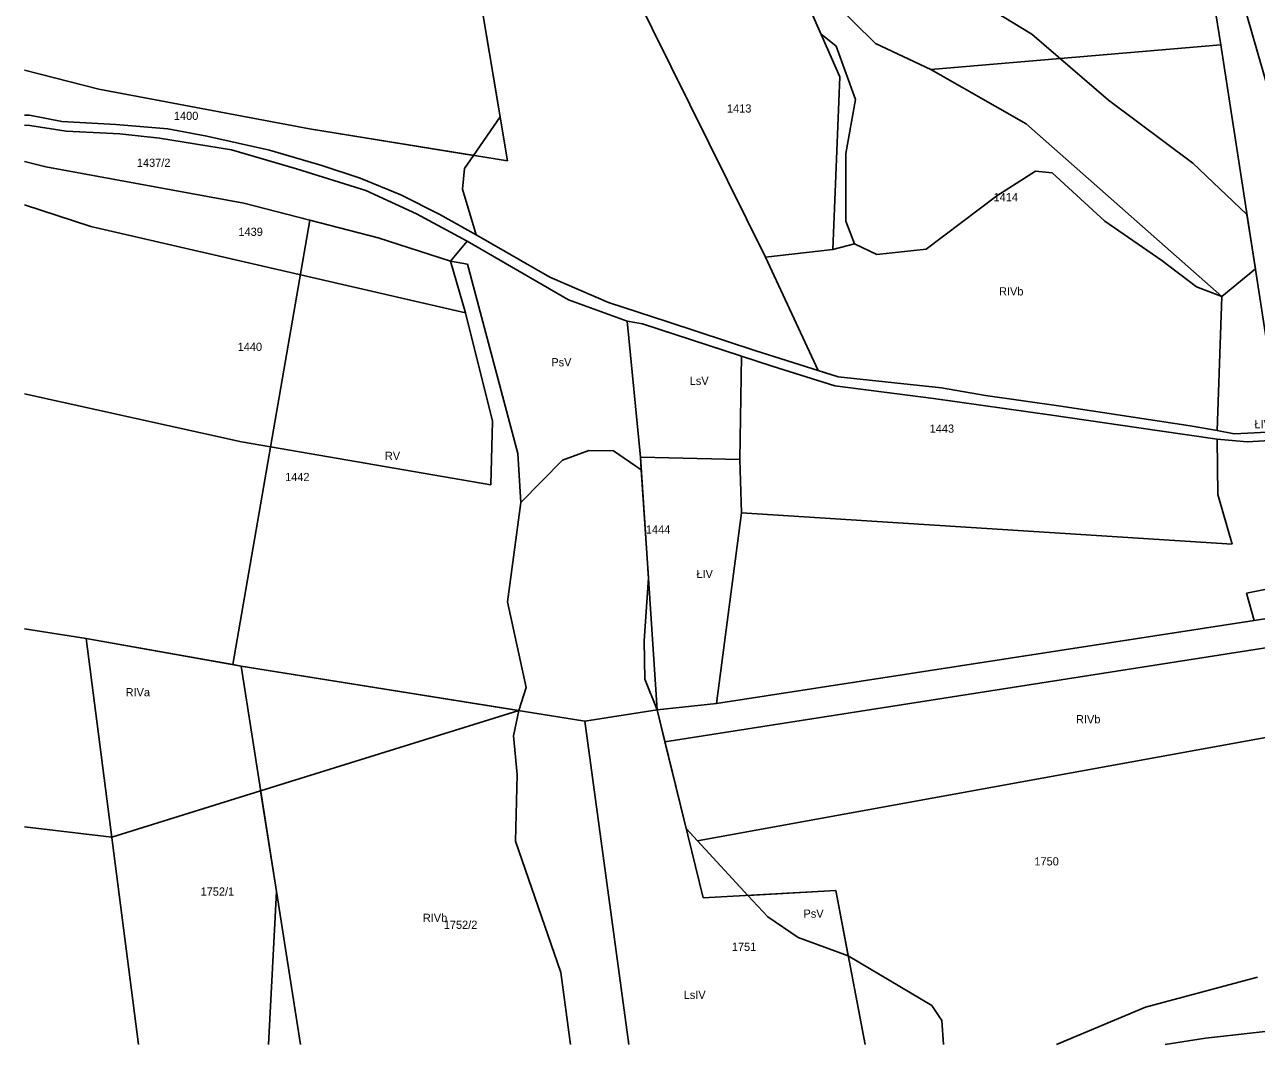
# Model space of a CAD drawing. Extents: x 7498273 to 7499989, y 5499795 to 5500810.
# Drawn here: x 7498273.2 to 7498498.5, y 5499795 to 5499981.5 of the extents above; entities that cross this region are included whole.
import ezdxf

# ---------------------------------------------------------------- set-up
doc = ezdxf.new("R2010")
doc.units = 0
for name, color, linetype in [('209-oznaczenie konturu klasyfikacyjnego', 7, 'Continuous'), ('211-numer działki ewidencyjnej', 7, 'Continuous'), ('217-kontur klasyfikacyjny', 7, 'Continuous'), ('218-kontur użytku gruntowego', 7, 'Continuous'), ('219-działka ewidencyjna', 7, 'Continuous')]:
    doc.layers.add(name, color=color, linetype=linetype)

msp = doc.modelspace()

# ---------------------------------------------------------------- linework, layer by layer
at = {"layer": '217-kontur klasyfikacyjny'}
for points in [[(7498492.44, 5499998.12), (7498509.38, 5499939.22)], [(7498354.96, 5499995.54), (7498360.15, 5499964.66)], [(7498408.66, 5499938.97), (7498380.98, 5499994.84)], [(7498418.82, 5499979.84), (7498412.52, 5499994.14)], [(7498457.42, 5499979.76), (7498434.61, 5499993.64)], [(7498421.58, 5499977.57), (7498418.82, 5499979.84)], [(7498471.4, 5499967.66), (7498457.42, 5499979.76)], [(7498425.12, 5499967.83), (7498421.58, 5499977.57)], [(7498286.77, 5499969.72), (7498273.174, 5499973.159)], [(7498325.25, 5499962.42), (7498286.77, 5499969.72)], [(7498423.36, 5499957.93), (7498425.12, 5499967.83)], [(7498486.83, 5499956.17), (7498471.4, 5499967.66)], [(7498273.174, 5499964.916), (7498274.04, 5499964.92)], [(7498274.1, 5499963.05), (7498273.174, 5499963.083)], [(7498274.04, 5499964.92), (7498280, 5499963.77)], [(7498280.77, 5499962.01), (7498274.1, 5499963.05)], [(7498280, 5499963.77), (7498289.88, 5499963.23)], [(7498289.88, 5499963.23), (7498299.34, 5499962.42)], [(7498360.15, 5499964.66), (7498355.27, 5499957.57)], [(7498290.57, 5499961.54), (7498280.77, 5499962.01)], [(7498297.84, 5499960.74), (7498290.57, 5499961.54)], [(7498311.03, 5499958.63), (7498297.84, 5499960.74)], [(7498299.34, 5499962.42), (7498306.49, 5499961.07)], [(7498306.49, 5499961.07), (7498317.96, 5499958.57)], [(7498355.27, 5499957.57), (7498325.25, 5499962.42)], [(7498322.89, 5499955.12), (7498311.03, 5499958.63)], [(7498317.96, 5499958.57), (7498327.52, 5499955.71)], [(7498277.07, 5499955.51), (7498273.174, 5499956.484)], [(7498355.27, 5499957.57), (7498353.64, 5499955.19)], [(7498423.37, 5499945.57), (7498423.36, 5499957.93)], [(7498496.74, 5499946.78), (7498486.83, 5499956.17)], [(7498313.28, 5499948.82), (7498277.07, 5499955.51)], [(7498335.56, 5499951.18), (7498322.89, 5499955.12)], [(7498327.52, 5499955.71), (7498334.52, 5499953.43)], [(7498353.64, 5499955.19), (7498353.27, 5499951.4)], [(7498451.01, 5499950.2), (7498458.04, 5499954.69)], [(7498458.04, 5499954.69), (7498461.14, 5499954.38)], [(7498461.14, 5499954.38), (7498470.75, 5499945.58)], [(7498334.52, 5499953.43), (7498341.99, 5499950.39)], [(7498344.87, 5499946.88), (7498335.56, 5499951.18)], [(7498341.99, 5499950.39), (7498349.09, 5499946.77)], [(7498353.27, 5499951.4), (7498355.77, 5499943.08)], [(7498438.1, 5499940.41), (7498451.01, 5499950.2)], [(7498325.35, 5499945.73), (7498313.28, 5499948.82)], [(7498311.26, 5499864.47), (7498325.35, 5499945.73)], [(7498337.86, 5499942.52), (7498325.35, 5499945.73)], [(7498354.11, 5499941.89), (7498344.87, 5499946.88)], [(7498349.09, 5499946.77), (7498355.77, 5499943.08)], [(7498424.96, 5499941.43), (7498423.37, 5499945.57)], [(7498470.75, 5499945.58), (7498481.19, 5499938.38)], [(7498498.28, 5499936.82), (7498496.74, 5499946.78)], [(7498355.77, 5499943.08), (7498369.24, 5499935.29)], [(7498351.05, 5499938.24), (7498337.86, 5499942.52)], [(7498354.11, 5499941.89), (7498351.05, 5499938.24)], [(7498372.63, 5499931.15), (7498354.11, 5499941.89)], [(7498408.66, 5499938.97), (7498421.01, 5499940.39)], [(7498421.01, 5499940.39), (7498424.96, 5499941.43)], [(7498424.96, 5499941.43), (7498429.05, 5499939.45)], [(7498429.05, 5499939.45), (7498438.1, 5499940.41)], [(7498354.17, 5499937.71), (7498351.05, 5499938.24)], [(7498418.29, 5499918.22), (7498408.66, 5499938.97)], [(7498481.19, 5499938.38), (7498487.52, 5499933.55)], [(7498363.38, 5499903.05), (7498354.17, 5499937.71)], [(7498492.13, 5499931.8), (7498498.28, 5499936.82)], [(7498369.24, 5499935.29), (7498379.95, 5499930.71)], [(7498487.52, 5499933.55), (7498492.13, 5499931.8)], [(7498491.3, 5499907.25), (7498492.13, 5499931.8)], [(7498383.38, 5499927.26), (7498372.63, 5499931.15)], [(7498379.95, 5499930.71), (7498390.84, 5499927.12)], [(7498385.8, 5499902.41), (7498383.38, 5499927.26)], [(7498386.19, 5499926.76), (7498383.38, 5499927.26)], [(7498390.84, 5499927.12), (7498406.9, 5499921.86)], [(7498404.28, 5499920.89), (7498386.19, 5499926.76)], [(7498404.01, 5499901.96), (7498404.28, 5499920.89)], [(7498409.92, 5499919.06), (7498404.28, 5499920.89)], [(7498406.9, 5499921.86), (7498418.29, 5499918.22)], [(7498421.37, 5499915.45), (7498409.92, 5499919.06)], [(7498418.29, 5499918.22), (7498421.95, 5499917.1)], [(7498421.95, 5499917.1), (7498440.9, 5499915.08)], [(7498439.43, 5499913.11), (7498421.37, 5499915.45)], [(7498440.9, 5499915.08), (7498448.94, 5499913.66)], [(7498448.94, 5499913.66), (7498462.71, 5499911.75)], [(7498461.03, 5499910.05), (7498439.43, 5499913.11)], [(7498462.71, 5499911.75), (7498486.33, 5499908.13)], [(7498480.32, 5499907.27), (7498461.03, 5499910.05)], [(7498491.31, 5499905.72), (7498480.32, 5499907.27)], [(7498486.33, 5499908.13), (7498491.3, 5499907.25)], [(7498491.3, 5499907.25), (7498494.41, 5499906.69)], [(7498494.41, 5499906.69), (7498502.88, 5499907.08)], [(7498496.76, 5499905.22), (7498491.31, 5499905.72)], [(7498506.1, 5499905.78), (7498496.76, 5499905.22)], [(7498363.96, 5499894.14), (7498363.38, 5499903.05)], [(7498371.56, 5499901.85), (7498376.39, 5499903.64)], [(7498376.39, 5499903.64), (7498380.88, 5499903.57)], [(7498380.88, 5499903.57), (7498385.96, 5499900.06)], [(7498385.96, 5499900.06), (7498385.8, 5499902.41)], [(7498385.8, 5499902.41), (7498404.01, 5499901.96)], [(7498363.96, 5499894.14), (7498371.56, 5499901.85)], [(7498387.26, 5499880.34), (7498385.96, 5499900.06)], [(7498404.29, 5499892.2), (7498404.01, 5499901.96)], [(7498361.47, 5499875.92), (7498363.96, 5499894.14)], [(7498399.75, 5499857.33), (7498404.29, 5499892.2)], [(7498386.47, 5499868.8), (7498387.26, 5499880.34)], [(7498364.88, 5499860.25), (7498361.47, 5499875.92)], [(7498522.06, 5499876.32), (7498498.06, 5499872.53)], [(7498390.29, 5499850.35), (7498536.44, 5499873.21)], [(7498273.174, 5499871.028), (7498284.45, 5499869.26)], [(7498498.06, 5499872.53), (7498399.75, 5499857.33)], [(7498284.45, 5499869.26), (7498311.26, 5499864.47)], [(7498386.64, 5499861.78), (7498386.47, 5499868.8)], [(7498312.75, 5499864.2), (7498311.26, 5499864.47)], [(7498363.59, 5499856.07), (7498312.75, 5499864.2)], [(7498388.86, 5499856.17), (7498386.64, 5499861.78)], [(7498363.59, 5499856.07), (7498364.88, 5499860.25)], [(7498388.86, 5499856.17), (7498399.75, 5499857.33)], [(7498316.34, 5499841.37), (7498363.59, 5499856.07)], [(7498362.57, 5499851.43), (7498363.59, 5499856.07)], [(7498390.29, 5499850.35), (7498388.86, 5499856.17)], [(7498396.23, 5499832.25), (7498509.2, 5499852.81)], [(7498363.26, 5499844.39), (7498362.57, 5499851.43)], [(7498394.17, 5499834.48), (7498390.29, 5499850.35)], [(7498362.96, 5499832.16), (7498363.26, 5499844.39)], [(7498316.34, 5499841.37), (7498289.14, 5499832.91)], [(7498319.23, 5499822.98), (7498316.34, 5499841.37)], [(7498289.14, 5499832.91), (7498273.174, 5499834.791)], [(7498396.23, 5499832.25), (7498394.17, 5499834.48)], [(7498405.44, 5499822.27), (7498396.23, 5499832.25)], [(7498371.24, 5499808.14), (7498362.96, 5499832.16)], [(7498405.44, 5499822.27), (7498421.52, 5499823.16)], [(7498421.52, 5499823.16), (7498423.82, 5499811.19)], [(7498317.762, 5499795.022), (7498319.23, 5499822.98)], [(7498409.08, 5499818.32), (7498405.44, 5499822.27)], [(7498414.63, 5499814.55), (7498409.08, 5499818.32)], [(7498423.82, 5499811.19), (7498414.63, 5499814.55)], [(7498439.12, 5499802.14), (7498423.82, 5499811.19)], [(7498372.991, 5499795.022), (7498371.24, 5499808.14)], [(7498498.65, 5499807.28), (7498478.18, 5499801.81)], [(7498440.95, 5499799.37), (7498439.12, 5499802.14)], [(7498478.18, 5499801.81), (7498461.907, 5499795.022)], [(7498441.257, 5499795.022), (7498440.95, 5499799.37)], [(7498489.18, 5499796.13), (7498526.87, 5499800.36)], [(7498481.788, 5499795.022), (7498489.18, 5499796.13)]]:
    msp.add_lwpolyline(points, dxfattribs=at)
at = {"layer": '218-kontur użytku gruntowego'}
for points in [[(7498492.44, 5499998.12), (7498509.38, 5499939.22)], [(7498360.15, 5499964.66), (7498354.96, 5499995.54)], [(7498380.98, 5499994.84), (7498408.66, 5499938.97)], [(7498412.52, 5499994.14), (7498418.82, 5499979.84)], [(7498457.42, 5499979.76), (7498434.61, 5499993.64)], [(7498418.82, 5499979.84), (7498421.58, 5499977.57)], [(7498471.4, 5499967.66), (7498457.42, 5499979.76)], [(7498421.58, 5499977.57), (7498425.12, 5499967.83)], [(7498273.174, 5499973.159), (7498286.77, 5499969.72)], [(7498286.77, 5499969.72), (7498325.25, 5499962.42)], [(7498425.12, 5499967.83), (7498423.36, 5499957.93)], [(7498486.83, 5499956.17), (7498471.4, 5499967.66)], [(7498273.174, 5499964.916), (7498274.04, 5499964.92)], [(7498274.1, 5499963.05), (7498273.174, 5499963.083)], [(7498274.04, 5499964.92), (7498280, 5499963.77)], [(7498280.77, 5499962.01), (7498274.1, 5499963.05)], [(7498280, 5499963.77), (7498289.88, 5499963.23)], [(7498289.88, 5499963.23), (7498299.34, 5499962.42)], [(7498355.27, 5499957.57), (7498360.15, 5499964.66)], [(7498290.57, 5499961.54), (7498280.77, 5499962.01)], [(7498297.84, 5499960.74), (7498290.57, 5499961.54)], [(7498311.03, 5499958.63), (7498297.84, 5499960.74)], [(7498299.34, 5499962.42), (7498306.49, 5499961.07)], [(7498306.49, 5499961.07), (7498317.96, 5499958.57)], [(7498325.25, 5499962.42), (7498355.27, 5499957.57)], [(7498322.89, 5499955.12), (7498311.03, 5499958.63)], [(7498317.96, 5499958.57), (7498327.52, 5499955.71)], [(7498277.07, 5499955.51), (7498273.174, 5499956.484)], [(7498353.64, 5499955.19), (7498355.27, 5499957.57)], [(7498423.36, 5499957.93), (7498423.37, 5499945.57)], [(7498496.74, 5499946.78), (7498486.83, 5499956.17)], [(7498313.28, 5499948.82), (7498277.07, 5499955.51)], [(7498335.56, 5499951.18), (7498322.89, 5499955.12)], [(7498327.52, 5499955.71), (7498334.52, 5499953.43)], [(7498353.27, 5499951.4), (7498353.64, 5499955.19)], [(7498458.04, 5499954.69), (7498451.01, 5499950.2)], [(7498461.14, 5499954.38), (7498458.04, 5499954.69)], [(7498470.75, 5499945.58), (7498461.14, 5499954.38)], [(7498334.52, 5499953.43), (7498341.99, 5499950.39)], [(7498344.87, 5499946.88), (7498335.56, 5499951.18)], [(7498341.99, 5499950.39), (7498349.09, 5499946.77)], [(7498355.77, 5499943.08), (7498353.27, 5499951.4)], [(7498451.01, 5499950.2), (7498438.1, 5499940.41)], [(7498325.35, 5499945.73), (7498313.28, 5499948.82)], [(7498325.35, 5499945.73), (7498311.26, 5499864.47)], [(7498337.86, 5499942.52), (7498325.35, 5499945.73)], [(7498354.11, 5499941.89), (7498344.87, 5499946.88)], [(7498349.09, 5499946.77), (7498355.77, 5499943.08)], [(7498423.37, 5499945.57), (7498424.96, 5499941.43)], [(7498481.19, 5499938.38), (7498470.75, 5499945.58)], [(7498498.28, 5499936.82), (7498496.74, 5499946.78)], [(7498355.77, 5499943.08), (7498369.24, 5499935.29)], [(7498351.05, 5499938.24), (7498337.86, 5499942.52)], [(7498354.11, 5499941.89), (7498351.05, 5499938.24)], [(7498372.63, 5499931.15), (7498354.11, 5499941.89)], [(7498421.01, 5499940.39), (7498408.66, 5499938.97)], [(7498424.96, 5499941.43), (7498421.01, 5499940.39)], [(7498429.05, 5499939.45), (7498424.96, 5499941.43)], [(7498438.1, 5499940.41), (7498429.05, 5499939.45)], [(7498351.05, 5499938.24), (7498354.17, 5499937.71)], [(7498408.66, 5499938.97), (7498418.29, 5499918.22)], [(7498487.52, 5499933.55), (7498481.19, 5499938.38)], [(7498354.17, 5499937.71), (7498363.38, 5499903.05)], [(7498492.13, 5499931.8), (7498498.28, 5499936.82)], [(7498369.24, 5499935.29), (7498379.95, 5499930.71)], [(7498492.13, 5499931.8), (7498487.52, 5499933.55)], [(7498491.3, 5499907.25), (7498492.13, 5499931.8)], [(7498383.38, 5499927.26), (7498372.63, 5499931.15)], [(7498379.95, 5499930.71), (7498390.84, 5499927.12)], [(7498383.38, 5499927.26), (7498385.8, 5499902.41)], [(7498386.19, 5499926.76), (7498383.38, 5499927.26)], [(7498390.84, 5499927.12), (7498406.9, 5499921.86)], [(7498404.28, 5499920.89), (7498386.19, 5499926.76)], [(7498404.28, 5499920.89), (7498404.01, 5499901.96)], [(7498409.92, 5499919.06), (7498404.28, 5499920.89)], [(7498406.9, 5499921.86), (7498418.29, 5499918.22)], [(7498421.37, 5499915.45), (7498409.92, 5499919.06)], [(7498418.29, 5499918.22), (7498421.95, 5499917.1)], [(7498421.95, 5499917.1), (7498440.9, 5499915.08)], [(7498439.43, 5499913.11), (7498421.37, 5499915.45)], [(7498440.9, 5499915.08), (7498448.94, 5499913.66)], [(7498448.94, 5499913.66), (7498462.71, 5499911.75)], [(7498461.03, 5499910.05), (7498439.43, 5499913.11)], [(7498462.71, 5499911.75), (7498486.33, 5499908.13)], [(7498480.32, 5499907.27), (7498461.03, 5499910.05)], [(7498491.31, 5499905.72), (7498480.32, 5499907.27)], [(7498486.33, 5499908.13), (7498491.3, 5499907.25)], [(7498494.41, 5499906.69), (7498491.3, 5499907.25)], [(7498502.88, 5499907.08), (7498494.41, 5499906.69)], [(7498496.76, 5499905.22), (7498491.31, 5499905.72)], [(7498506.1, 5499905.78), (7498496.76, 5499905.22)], [(7498363.38, 5499903.05), (7498363.96, 5499894.14)], [(7498376.39, 5499903.64), (7498371.56, 5499901.85)], [(7498380.88, 5499903.57), (7498376.39, 5499903.64)], [(7498385.96, 5499900.06), (7498380.88, 5499903.57)], [(7498385.8, 5499902.41), (7498404.01, 5499901.96)], [(7498385.8, 5499902.41), (7498385.96, 5499900.06)], [(7498371.56, 5499901.85), (7498363.96, 5499894.14)], [(7498385.96, 5499900.06), (7498387.26, 5499880.34)], [(7498404.01, 5499901.96), (7498404.29, 5499892.2)], [(7498363.96, 5499894.14), (7498361.47, 5499875.92)], [(7498404.29, 5499892.2), (7498399.75, 5499857.33)], [(7498387.26, 5499880.34), (7498386.47, 5499868.8)], [(7498361.47, 5499875.92), (7498364.88, 5499860.25)], [(7498498.06, 5499872.53), (7498522.06, 5499876.32)], [(7498536.44, 5499873.21), (7498390.29, 5499850.35)], [(7498284.45, 5499869.26), (7498273.174, 5499871.028)], [(7498399.75, 5499857.33), (7498498.06, 5499872.53)], [(7498311.26, 5499864.47), (7498284.45, 5499869.26)], [(7498386.47, 5499868.8), (7498386.64, 5499861.78)], [(7498311.26, 5499864.47), (7498312.75, 5499864.2)], [(7498312.75, 5499864.2), (7498363.59, 5499856.07)], [(7498386.64, 5499861.78), (7498388.86, 5499856.17)], [(7498364.88, 5499860.25), (7498363.59, 5499856.07)], [(7498388.86, 5499856.17), (7498399.75, 5499857.33)], [(7498363.59, 5499856.07), (7498316.34, 5499841.37)], [(7498363.59, 5499856.07), (7498362.57, 5499851.43)], [(7498388.86, 5499856.17), (7498390.29, 5499850.35)], [(7498396.23, 5499832.25), (7498509.2, 5499852.81)], [(7498362.57, 5499851.43), (7498363.26, 5499844.39)], [(7498390.29, 5499850.35), (7498394.17, 5499834.48)], [(7498363.26, 5499844.39), (7498362.96, 5499832.16)], [(7498289.14, 5499832.91), (7498316.34, 5499841.37)], [(7498316.34, 5499841.37), (7498319.23, 5499822.98)], [(7498273.174, 5499834.791), (7498289.14, 5499832.91)], [(7498394.17, 5499834.48), (7498396.23, 5499832.25)], [(7498396.23, 5499832.25), (7498405.44, 5499822.27)], [(7498362.96, 5499832.16), (7498371.24, 5499808.14)], [(7498405.44, 5499822.27), (7498421.52, 5499823.16)], [(7498421.52, 5499823.16), (7498423.82, 5499811.19)], [(7498319.23, 5499822.98), (7498317.762, 5499795.022)], [(7498405.44, 5499822.27), (7498409.08, 5499818.32)], [(7498409.08, 5499818.32), (7498414.63, 5499814.55)], [(7498414.63, 5499814.55), (7498423.82, 5499811.19)], [(7498423.82, 5499811.19), (7498439.12, 5499802.14)], [(7498371.24, 5499808.14), (7498372.991, 5499795.022)], [(7498478.18, 5499801.81), (7498498.65, 5499807.28)], [(7498439.12, 5499802.14), (7498440.95, 5499799.37)], [(7498461.907, 5499795.022), (7498478.18, 5499801.81)], [(7498440.95, 5499799.37), (7498441.257, 5499795.022)], [(7498489.18, 5499796.13), (7498526.87, 5499800.36)], [(7498481.788, 5499795.022), (7498489.18, 5499796.13)]]:
    msp.add_lwpolyline(points, dxfattribs=at)
at = {"layer": '219-działka ewidencyjna'}
for points in [[(7498491.95, 5499977.81), (7498488.72, 5499997.94)], [(7498509.38, 5499939.22), (7498492.44, 5499998.12)], [(7498354.96, 5499995.54), (7498361.51, 5499956.56)], [(7498380.98, 5499994.84), (7498408.66, 5499938.97)], [(7498412.52, 5499994.14), (7498422.29, 5499971.97)], [(7498412.52, 5499994.14), (7498428.82, 5499978.05)], [(7498428.82, 5499978.05), (7498438.92, 5499973.31)], [(7498438.92, 5499973.31), (7498491.95, 5499977.81)], [(7498491.95, 5499977.81), (7498502.88, 5499907.08)], [(7498273.174, 5499973.158), (7498286.77, 5499969.72)], [(7498421.01, 5499940.39), (7498422.29, 5499971.97)], [(7498456.34, 5499963.34), (7498438.92, 5499973.31)], [(7498286.77, 5499969.72), (7498325.25, 5499962.42)], [(7498273.174, 5499964.916), (7498274.04, 5499964.92)], [(7498274.1, 5499963.05), (7498273.174, 5499963.083)], [(7498274.04, 5499964.92), (7498280, 5499963.77)], [(7498274.1, 5499963.05), (7498280.77, 5499962.01)], [(7498280, 5499963.77), (7498289.88, 5499963.23)], [(7498289.88, 5499963.23), (7498299.34, 5499962.42)], [(7498456.34, 5499963.34), (7498492.13, 5499931.8)], [(7498280.77, 5499962.01), (7498290.57, 5499961.54)], [(7498290.57, 5499961.54), (7498297.84, 5499960.74)], [(7498297.84, 5499960.74), (7498311.03, 5499958.63)], [(7498299.34, 5499962.42), (7498306.49, 5499961.07)], [(7498306.49, 5499961.07), (7498317.96, 5499958.57)], [(7498325.25, 5499962.42), (7498361.51, 5499956.56)], [(7498322.89, 5499955.12), (7498311.03, 5499958.63)], [(7498317.96, 5499958.57), (7498327.52, 5499955.71)], [(7498273.174, 5499956.484), (7498277.07, 5499955.51)], [(7498277.07, 5499955.51), (7498313.28, 5499948.82)], [(7498322.89, 5499955.12), (7498335.56, 5499951.18)], [(7498327.52, 5499955.71), (7498334.52, 5499953.43)], [(7498334.52, 5499953.43), (7498341.99, 5499950.39)], [(7498344.87, 5499946.88), (7498335.56, 5499951.18)], [(7498341.99, 5499950.39), (7498349.09, 5499946.77)], [(7498273.174, 5499948.538), (7498285.29, 5499944.56)], [(7498313.28, 5499948.82), (7498337.86, 5499942.52)], [(7498344.87, 5499946.88), (7498354.11, 5499941.89)], [(7498349.09, 5499946.77), (7498355.77, 5499943.08)], [(7498285.29, 5499944.56), (7498353.79, 5499928.77)], [(7498355.77, 5499943.08), (7498369.24, 5499935.29)], [(7498337.86, 5499942.52), (7498351.05, 5499938.24)], [(7498351.05, 5499938.24), (7498354.11, 5499941.89)], [(7498354.11, 5499941.89), (7498372.63, 5499931.15)], [(7498408.66, 5499938.97), (7498421.01, 5499940.39)], [(7498351.05, 5499938.24), (7498353.79, 5499928.77)], [(7498408.66, 5499938.97), (7498418.29, 5499918.22)], [(7498369.24, 5499935.29), (7498379.95, 5499930.71)], [(7498491.3, 5499907.25), (7498492.13, 5499931.8)], [(7498372.63, 5499931.15), (7498383.38, 5499927.26)], [(7498379.95, 5499930.71), (7498390.84, 5499927.12)], [(7498353.79, 5499928.77), (7498358.72, 5499909)], [(7498383.38, 5499927.26), (7498386.19, 5499926.76)], [(7498383.38, 5499927.26), (7498385.8, 5499902.41)], [(7498390.84, 5499927.12), (7498406.9, 5499921.86)], [(7498386.19, 5499926.76), (7498409.92, 5499919.06)], [(7498406.9, 5499921.86), (7498418.29, 5499918.22)], [(7498421.37, 5499915.45), (7498409.92, 5499919.06)], [(7498418.29, 5499918.22), (7498421.95, 5499917.1)], [(7498421.95, 5499917.1), (7498440.9, 5499915.08)], [(7498273.174, 5499913.986), (7498312.86, 5499905.21)], [(7498421.37, 5499915.45), (7498439.43, 5499913.11)], [(7498448.94, 5499913.66), (7498440.9, 5499915.08)], [(7498448.94, 5499913.66), (7498462.71, 5499911.75)], [(7498439.43, 5499913.11), (7498461.03, 5499910.05)], [(7498462.71, 5499911.75), (7498486.33, 5499908.13)], [(7498358.42, 5499897.33), (7498358.72, 5499909)], [(7498461.03, 5499910.05), (7498480.32, 5499907.27)], [(7498480.32, 5499907.27), (7498491.31, 5499905.72)], [(7498486.33, 5499908.13), (7498491.3, 5499907.25)], [(7498491.3, 5499907.25), (7498494.41, 5499906.69)], [(7498494.41, 5499906.69), (7498502.88, 5499907.08)], [(7498312.86, 5499905.21), (7498358.42, 5499897.33)], [(7498491.31, 5499905.72), (7498496.76, 5499905.22)], [(7498491.31, 5499905.72), (7498491.4, 5499895.6)], [(7498496.76, 5499905.22), (7498506.1, 5499905.78)], [(7498385.8, 5499902.41), (7498404.01, 5499901.96)], [(7498385.8, 5499902.41), (7498388.86, 5499856.17)], [(7498404.01, 5499901.96), (7498404.29, 5499892.2)], [(7498491.4, 5499895.6), (7498494.04, 5499886.47)], [(7498496.65, 5499877.51), (7498575.4, 5499893.4)], [(7498404.29, 5499892.2), (7498494.04, 5499886.47)], [(7498496.65, 5499877.51), (7498498.06, 5499872.53)], [(7498498.06, 5499872.53), (7498522.06, 5499876.32)], [(7498273.174, 5499871.028), (7498284.45, 5499869.26)], [(7498399.75, 5499857.33), (7498498.06, 5499872.53)], [(7498284.45, 5499869.26), (7498312.75, 5499864.2)], [(7498284.45, 5499869.26), (7498294.022, 5499795.022)], [(7498312.75, 5499864.2), (7498323.62, 5499795.022)], [(7498312.75, 5499864.2), (7498375.64, 5499854.15)], [(7498399.75, 5499857.33), (7498388.86, 5499856.17)], [(7498375.64, 5499854.15), (7498388.86, 5499856.17)], [(7498388.86, 5499856.17), (7498397.27, 5499821.82)], [(7498383.668, 5499795.022), (7498375.64, 5499854.15)], [(7498397.27, 5499821.82), (7498421.52, 5499823.16)], [(7498426.934, 5499795.022), (7498421.52, 5499823.16)], [(7498489.18, 5499796.13), (7498526.87, 5499800.36)], [(7498481.788, 5499795.022), (7498489.18, 5499796.13)]]:
    msp.add_lwpolyline(points, dxfattribs=at)

# ---------------------------------------------------------------- texts
at = {"layer": '209-oznaczenie konturu klasyfikacyjnego'}
for s, p in [('RIVb', (7498451.4, 5499931.97)), ('PsV', (7498369.51, 5499919.02)), ('LsV', (7498394.83, 5499915.61)), ('ŁIV', (7498498.11, 5499907.69)), ('RV', (7498339.07, 5499901.9)), ('ŁIV', (7498396.05, 5499880.29)), ('RIVa', (7498291.65, 5499858.67)), ('RIVb', (7498465.48, 5499853.73)), ('RIVb', (7498346.01, 5499817.41)), ('PsV', (7498415.63, 5499818.18)), ('LsIV', (7498393.72, 5499803.32))]:
    msp.add_text(s, height=1.5, dxfattribs=at).set_placement(p)
at = {"layer": '211-numer działki ewidencyjnej'}
for s, p in [('1400', (7498300.48, 5499964.07)), ('1413', (7498401.64, 5499965.41)), ('1437/2', (7498293.71, 5499955.49)), ('1414', (7498450.4, 5499949.2)), ('1439', (7498312.28, 5499942.86)), ('1440', (7498312.14, 5499921.83)), ('1443', (7498438.71, 5499906.87)), ('1442', (7498320.82, 5499898.02)), ('1444', (7498386.8, 5499888.42)), ('1750', (7498457.87, 5499827.74)), ('1752/1', (7498305.36, 5499822.21)), ('1752/2', (7498349.84, 5499816.14)), ('1751', (7498402.53, 5499812.12))]:
    msp.add_text(s, height=1.5, dxfattribs=at).set_placement(p)

doc.saveas('drawing.dxf')
